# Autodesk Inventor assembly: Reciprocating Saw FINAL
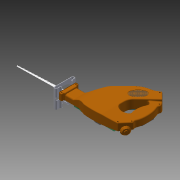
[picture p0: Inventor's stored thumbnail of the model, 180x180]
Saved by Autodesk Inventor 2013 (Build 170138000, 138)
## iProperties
Created: 2008-06
Part Number: Reciprocating Saw FINAL
Document SubType Name: Assembly
Designer: tangg
Mass: 944.675 g
Surface Area: 4194.83 cm^2
Volume: 272.559 cm^3
Density: 3.46595 g/cm^3
Author: tangg
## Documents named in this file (12)
- C:\Users\boganb\Documents\B2 Design\Goodyear\2013 Tutorial Files\Dynamic Simulation 1 and 2\Reciprocating Saw FINAL.iam
- C:\Users\boganb\Documents\B2 Design\Goodyear\2013 Tutorial Files\Dynamic Simulation 1 and 2\Saw layout.ipt
- C:\Users\boganb\Documents\B2 Design\Goodyear\2013 Tutorial Files\Dynamic Simulation 1 and 2\Guide.ipt
- C:\Users\boganb\Documents\B2 Design\Goodyear\2013 Tutorial Files\Dynamic Simulation 1 and 2\Motor housing.ipt
- C:\Users\boganb\Documents\B2 Design\Goodyear\2013 Tutorial Files\Dynamic Simulation 1 and 2\Case.ipt
- C:\Users\boganb\Documents\B2 Design\Goodyear\2013 Tutorial Files\Dynamic Simulation 1 and 2\Follower.ipt
- C:\Users\boganb\Documents\B2 Design\Goodyear\2013 Tutorial Files\Dynamic Simulation 1 and 2\Fence.ipt
- C:\Users\boganb\Documents\B2 Design\Goodyear\2013 Tutorial Files\Dynamic Simulation 1 and 2\Cam crank.iam
- C:\Users\boganb\Documents\B2 Design\Goodyear\2013 Tutorial Files\Dynamic Simulation 1 and 2\Motor.iam
- C:\Users\boganb\Documents\B2 Design\Goodyear\2013 Tutorial Files\Dynamic Simulation 1 and 2\Follower Roller.ipt
- C:\Users\boganb\Documents\B2 Design\Goodyear\2013 Tutorial Files\Dynamic Simulation 1 and 2\SKFRLS 4 A-2ZANSI.ipt
- C:\Users\boganb\Documents\B2 Design\Goodyear\2013 Tutorial Files\Dynamic Simulation 1 and 2\Blade set.iam
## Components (12 placed, 11 different names)
1. Saw layout:1 — Flush:15, Mate:66, Mate:76, Mate:77
2. Case:1 — Flush:16, Mate:74, Flush:19, Flush:20
3. Fence:1 — Flush:16, Mate:74
4. Guide:1 — Flush:15, Mate:71, Mate:72, Mate:88, Mate:89
5. SKF Series RLS- with Two Shields RLS 4 A-2Z:1 — Flush:19
6. SKF Series RLS- with Two Shields RLS 4 A-2Z:2 — Flush:20
7. Motor housing:1 — Mate:66, Mate:73
8. Cam crank:1 [sub-assembly] — Mate:76, Mate:77, Mate:90
9. Motor:1 [sub-assembly] — Mate:73
10. Follower:1 — Mate:71, Mate:72, Mate:75, Flush:17
11. Follower Roller:1 — Mate:75, Flush:17
12. Blade set:1 [sub-assembly] — Mate:88, Mate:89, Mate:90
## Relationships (16: Mate 11, Flush 5)
- Flush:15: Saw layout:1 ↔ Guide:1
- Flush:16: Case:1 ↔ Fence:1
- Mate:66: Saw layout:1 ↔ Motor housing:1
- Mate:71: Guide:1 ↔ Follower:1
- Mate:72: Guide:1 ↔ Follower:1
- Mate:73: Motor housing:1 ↔ Motor:1
- Mate:74: Case:1 ↔ Fence:1
- Mate:75: Follower:1 ↔ Follower Roller:1
- Flush:17: Follower:1 ↔ Follower Roller:1
- Mate:76: Saw layout:1 ↔ Cam crank:1
- Mate:77: Saw layout:1 ↔ Cam crank:1
- Flush:19: Case:1 ↔ SKF Series RLS- with Two Shields RLS 4 A-2Z:1
- Flush:20: Case:1 ↔ SKF Series RLS- with Two Shields RLS 4 A-2Z:2
- Mate:88: Guide:1 ↔ Blade set:1
- Mate:89: Guide:1 ↔ Blade set:1
- Mate:90: Cam crank:1 ↔ Blade set:1
